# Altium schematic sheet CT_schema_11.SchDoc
size 405 x 220 mm
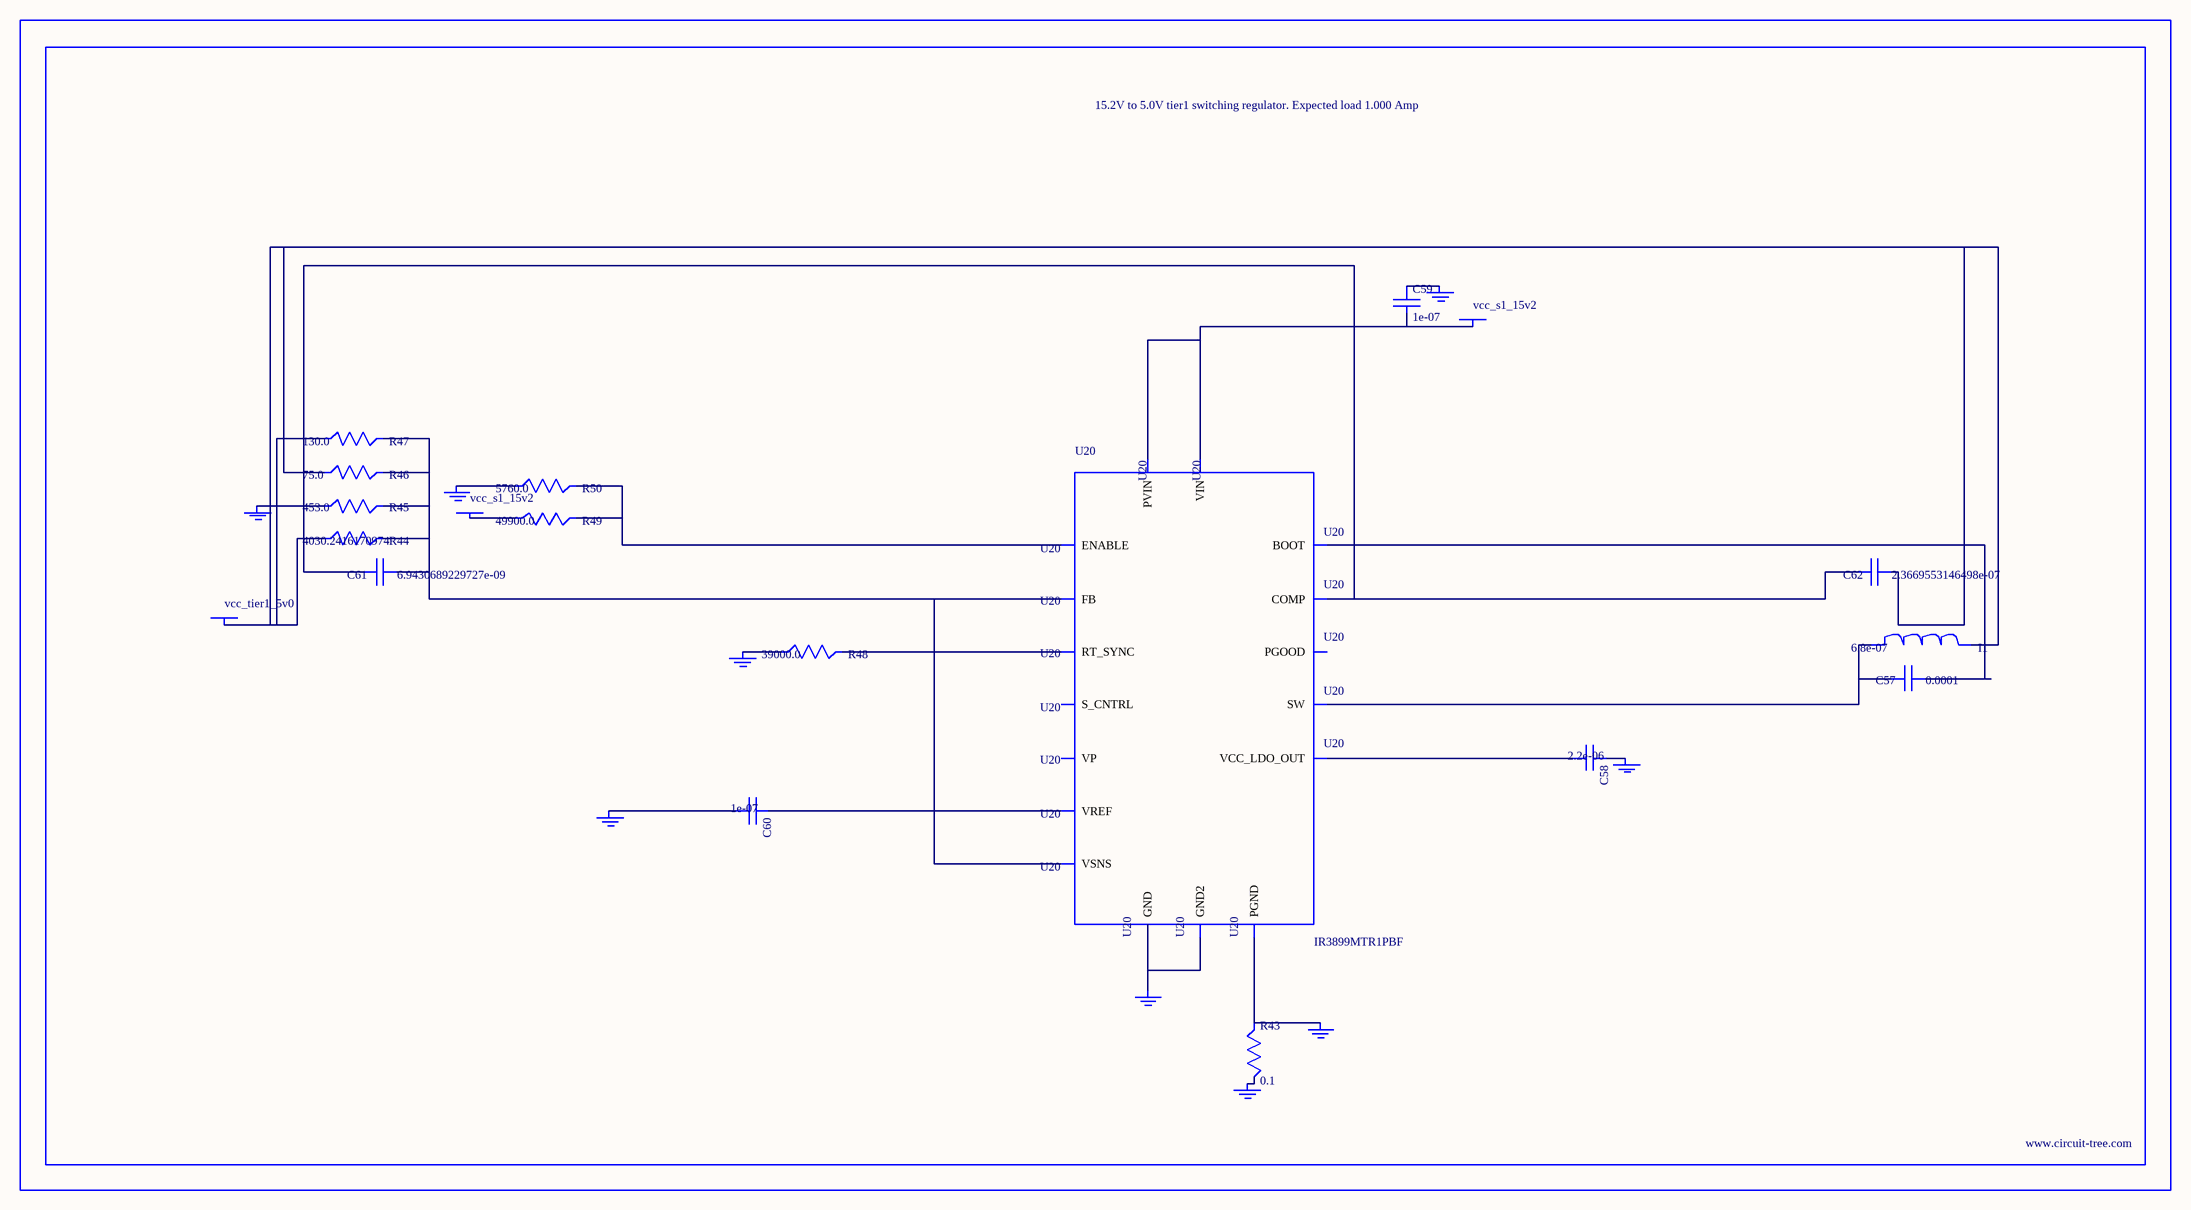
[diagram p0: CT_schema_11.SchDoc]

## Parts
BORDER10  (no value)
C57  0.0001  [C1210]
C58  2.2e-06  [C0603]
C59  1e-07  [C0402]
C60  1e-07  [C0402]
C61  6.9430689229727e-09  [R0603]
C62  2.3669553146498e-07  [R0603]
GND_INSTANCE_10_0  (no value)
GND_INSTANCE_10_1  (no value)
GND_INSTANCE_10_2  (no value)
GND_INSTANCE_10_3  (no value)
GND_INSTANCE_10_4  (no value)
GND_INSTANCE_10_5  (no value)
GND_INSTANCE_10_6  (no value)
GND_INSTANCE_10_7  (no value)
GND_INSTANCE_10_8  (no value)
I1  6.8e-07  [IND25X25CZ]
POWER_INSTANCE_10_0  vcc_s1_15v2
POWER_INSTANCE_10_1  vcc_s1_15v2
POWER_INSTANCE_10_2  vcc_tier1_5v0
R43  0.1  [R0603]
R44  4030.2416170974  [R0603]
R45  453.0  [R0603]
R46  75.0  [R0603]
R47  130.0  [R0603]
R48  39000.0  [R0603]
R49  49900.0  [R0603]
R50  5760.0  [R0603]
U20  IR3899MTR1PBF  [IR3899MTR1PBF]

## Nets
NetC57_1: C57.1 U20.14(BOOT)
NetC57_2: C57.2 I1.1 U20.12(SW)
NetC58_1: C58.1 GND_INSTANCE_10_4.0(GND)
NetC58_2: C58.2 U20.10(VCC_LDO_OUT)
NetC59_1: C59.1 GND_INSTANCE_10_3.0(GND)
NetC59_2: C59.2 POWER_INSTANCE_10_0.0(PWR) U20.9(VIN) U20.13(PVIN)
NetC60_1: C60.1 U20.2(VREF)
NetC60_2: C60.2 GND_INSTANCE_10_1.0(GND)
NetC61_1: C61.1 R44.2 R45.2 R46.2 R47.2 U20.1(FB) U20.8(VSNS)
NetC61_2: C61.2 C62.2 U20.3(COMP)
NetC62_1: C62.1 I1.2 POWER_INSTANCE_10_2.0(PWR) R44.1 R46.1 R47.1
NetGND_INSTANCE_10_0_0: GND_INSTANCE_10_0.0(GND) R45.1
NetGND_INSTANCE_10_2_0: GND_INSTANCE_10_2.0(GND) R48.1
NetGND_INSTANCE_10_5_0: GND_INSTANCE_10_5.0(GND) R43.2
NetGND_INSTANCE_10_6_0: GND_INSTANCE_10_6.0(GND) R43.1 U20.11(PGND)
NetGND_INSTANCE_10_7_0: GND_INSTANCE_10_7.0(GND) R50.1
NetGND_INSTANCE_10_8_0: GND_INSTANCE_10_8.0(GND) U20.4(GND) U20.17(GND2)
NetPOWER_INSTANCE_10_1_0: POWER_INSTANCE_10_1.0(PWR) R49.1
NetR48_2: R48.2 U20.5(RT_SYNC)
NetR49_2: R49.2 R50.2 U20.15(ENABLE)

Not connected (* = marked no-connect by the designer): U20 6(S_CNTRL) 7(PGOOD) 16(VP)

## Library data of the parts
BORDER10 = BORDER_PAGE10
C57 = GRM32ER61A107ME20L
C58 = C0603C225K8RACTU
C59 C60 = C0402C104K3RACTU
C61 = C61
C62 = C62
GND_INSTANCE_10_0-GND_INSTANCE_10_8 = GND
I1 = IHLP2525CZERR68M01
POWER_INSTANCE_10_0-POWER_INSTANCE_10_2 = PWR
R43 = ERJ-3RSFR10V
R44 = R44
R45 = ERJ-3EKF4530V
R46 = RC0603JR-0775RL
R47 = RC0603JR-07130RL
R48 = RC0603JR-0739KL
R49 = RC0603FR-0749K9
R50 = ERJ-3EKF5760V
